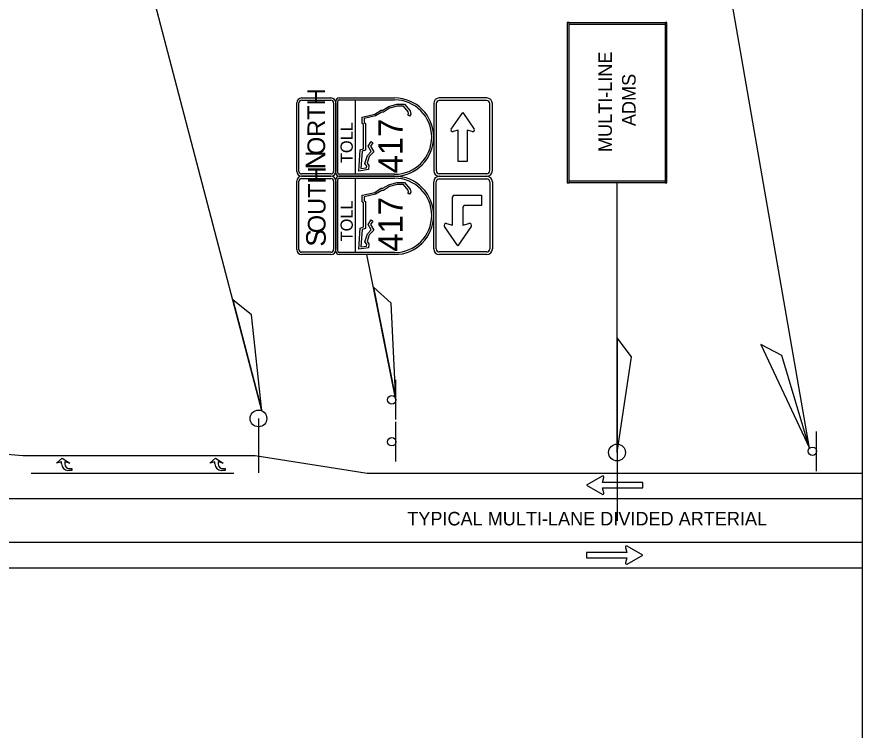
# Model space of a CAD drawing. Extents: x -830008.4 to -829992.7, y 1290284.1 to 1290294.4.
# Drawn here: x -829997.148 to -829992.774, y 1290288.685 to 1290292.375 of the extents above; entities that cross this region are included whole.
import ezdxf

# ---------------------------------------------------------------- set-up
doc = ezdxf.new("R2010")
doc.units = 0
for name, color, linetype in [('DirArrowsPavt', 7, 'Continuous'), ('LaneDirArrow', 7, 'Continuous'), ('LeaderLine_dp', 7, 'Continuous'), ('NonPlottingEle_dp', 7, 'Continuous'), ('SignPanel', 7, 'Continuous'), ('SignSupport', 7, 'Continuous'), ('SignTruss', 7, 'Continuous'), ('TextLabel', 7, 'Continuous')]:
    doc.layers.add(name, color=color, linetype=linetype)

msp = doc.modelspace()

# ---------------------------------------------------------------- linework, layer by layer
at = {"layer": 'DirArrowsPavt'}
for p, q in [((-829996.8778, 1290290.0388), (-829996.8642, 1290290.0388)), ((-829996.0841, 1290290.0388), (-829996.0704, 1290290.0388))]:
    msp.add_line(p, q, dxfattribs=at)
for points in [[(-829996.9175, 1290290.0616), (-829996.9175, 1290290.0721), (-829996.9442, 1290290.0655), (-829996.9142, 1290290.0921), (-829996.8742, 1290290.0655), (-829996.9008, 1290290.0721), (-829996.9008, 1290290.0618)], [(-829996.1237, 1290290.0616), (-829996.1237, 1290290.0721), (-829996.1504, 1290290.0655), (-829996.1204, 1290290.0921), (-829996.0804, 1290290.0655), (-829996.1071, 1290290.0721), (-829996.1071, 1290290.0618)], [(-829996.8642, 1290290.0388), (-829996.8642, 1290290.0288), (-829996.8847, 1290290.0288)], [(-829996.0704, 1290290.0388), (-829996.0704, 1290290.0288), (-829996.0909, 1290290.0288)]]:
    msp.add_lwpolyline(points, dxfattribs=at)
for centre, radius in [((-829996.8847, 1290290.0616), 0.0328), ((-829996.8778, 1290290.0618), 0.023), ((-829996.0909, 1290290.0616), 0.0328), ((-829996.0841, 1290290.0618), 0.023)]:
    msp.add_arc(centre, radius, 180, 270, dxfattribs=at)
at = {"layer": 'LaneDirArrow'}
for p, q in [((-829994.1196, 1290289.9986), (-829994.2004, 1290289.952)), ((-829994.1173, 1290289.9659), (-829994.1105, 1290289.9916)), ((-829993.9087, 1290289.9659), (-829994.1173, 1290289.9659)), ((-829993.9087, 1290289.9381), (-829993.9087, 1290289.9659)), ((-829994.2004, 1290289.952), (-829994.1196, 1290289.9054)), ((-829994.1173, 1290289.9381), (-829993.9087, 1290289.9381)), ((-829994.1105, 1290289.9124), (-829994.1173, 1290289.9381)), ((-829993.9986, 1290289.6301), (-829993.9917, 1290289.6044)), ((-829993.9087, 1290289.5905), (-829993.9895, 1290289.6372)), ((-829993.9917, 1290289.6044), (-829994.2004, 1290289.6044)), ((-829994.2004, 1290289.6044), (-829994.2004, 1290289.5767)), ((-829994.2004, 1290289.5767), (-829993.9917, 1290289.5767)), ((-829993.9917, 1290289.5767), (-829993.9986, 1290289.551)), ((-829993.9895, 1290289.5439), (-829993.9087, 1290289.5905))]:
    msp.add_line(p, q, dxfattribs=at)
for centre, start, end in [((-829994.1165, 1290289.9932), 345, 120), ((-829994.1165, 1290289.9108), 240, 15), ((-829993.9926, 1290289.6318), 60, 195), ((-829993.9926, 1290289.5493), 165, 300)]:
    msp.add_arc(centre, 0.00625, start, end, dxfattribs=at)
at = {"layer": 'LeaderLine_dp'}
for p, q in [((-829995.2111, 1290290.8933), (-829995.3033, 1290290.9757)), ((-829995.3033, 1290290.9757), (-829995.1866, 1290290.3939)), ((-829995.9337, 1290290.8338), (-829996.0305, 1290290.9106)), ((-829996.0305, 1290290.9106), (-829995.8801, 1290290.3367)), ((-829995.1866, 1290290.3939), (-829995.2111, 1290290.8933)), ((-829995.8801, 1290290.3367), (-829995.9337, 1290290.8338)), ((-829993.9683, 1290290.6153), (-829994.0424, 1290290.7142)), ((-829994.0424, 1290290.7142), (-829994.0424, 1290290.1209)), ((-829993.189, 1290290.6224), (-829993.298, 1290290.6806)), ((-829993.298, 1290290.6806), (-829993.0471, 1290290.1429)), ((-829994.0424, 1290290.1209), (-829993.9683, 1290290.6153)), ((-829993.0471, 1290290.1429), (-829993.189, 1290290.6224))]:
    msp.add_line(p, q, dxfattribs=at)
at = {"layer": 'NonPlottingEle_dp'}
msp.add_lwpolyline([(-830007.4742, 1290294.228), (-829992.7742, 1290294.228), (-829992.7742, 1290285.328), (-830007.4742, 1290285.328)], close=True, dxfattribs=at)
at = {"layer": 'SignPanel'}
for p, q in [((-829995.2966, 1290291.8721), (-829995.2632, 1290291.8929)), ((-829995.2602, 1290291.8823), (-829995.2925, 1290291.8622)), ((-829995.2632, 1290291.8929), (-829995.2548, 1290291.8929)), ((-829995.2518, 1290291.8823), (-829995.2602, 1290291.8823)), ((-829995.2548, 1290291.8929), (-829995.2238, 1290291.9117)), ((-829995.2196, 1290291.9019), (-829995.2518, 1290291.8823)), ((-829995.2238, 1290291.9117), (-829995.1814, 1290291.9233)), ((-829995.18, 1290291.9127), (-829995.2196, 1290291.9019)), ((-829995.1814, 1290291.9233), (-829995.1418, 1290291.9233)), ((-829995.1468, 1290291.9127), (-829995.18, 1290291.9127)), ((-829995.1232, 1290291.8839), (-829995.1468, 1290291.9127)), ((-829995.1418, 1290291.9233), (-829995.1135, 1290291.8887)), ((-829995.1209, 1290291.8745), (-829995.1232, 1290291.8839)), ((-829995.1135, 1290291.8887), (-829995.1095, 1290291.8723)), ((-829994.9003, 1290291.7947), (-829994.8411, 1290291.8809)), ((-829994.8411, 1290291.8809), (-829994.7819, 1290291.7947)), ((-829995.3624, 1290291.8568), (-829995.2966, 1290291.8721)), ((-829995.3624, 1290291.823), (-829995.3624, 1290291.8568)), ((-829995.2925, 1290291.8622), (-829995.3518, 1290291.8484)), ((-829995.3518, 1290291.8484), (-829995.3518, 1290291.8286)), ((-829995.1254, 1290291.8679), (-829995.1209, 1290291.8745)), ((-829995.1168, 1290291.8619), (-829995.1254, 1290291.8679)), ((-829995.1095, 1290291.8723), (-829995.1168, 1290291.8619)), ((-829995.3554, 1290291.8183), (-829995.3624, 1290291.823)), ((-829995.3554, 1290291.6929), (-829995.3554, 1290291.8183)), ((-829995.3518, 1290291.8286), (-829995.3448, 1290291.8239)), ((-829995.3448, 1290291.8239), (-829995.3448, 1290291.6857)), ((-829994.8639, 1290291.7895), (-829994.8907, 1290291.7815)), ((-829994.8639, 1290291.6271), (-829994.8639, 1290291.7895)), ((-829994.7915, 1290291.7815), (-829994.8183, 1290291.7895)), ((-829994.8183, 1290291.7895), (-829994.8183, 1290291.6271)), ((-829995.3313, 1290291.7065), (-829995.3158, 1290291.7293)), ((-829995.3148, 1290291.6784), (-829995.3313, 1290291.7065)), ((-829995.3071, 1290291.7234), (-829995.3188, 1290291.7061)), ((-829995.3188, 1290291.7061), (-829995.3017, 1290291.677)), ((-829995.3158, 1290291.7293), (-829995.3071, 1290291.7234)), ((-829995.3795, 1290291.5774), (-829995.3711, 1290291.6868)), ((-829995.3711, 1290291.6868), (-829995.3554, 1290291.6929)), ((-829995.3611, 1290291.6793), (-829995.368, 1290291.5899)), ((-829995.3448, 1290291.6857), (-829995.3611, 1290291.6793)), ((-829995.334, 1290291.6577), (-829995.3148, 1290291.6784)), ((-829995.3017, 1290291.677), (-829995.3247, 1290291.6522)), ((-829995.3477, 1290291.6155), (-829995.334, 1290291.6577)), ((-829995.3247, 1290291.6522), (-829995.3359, 1290291.6176)), ((-829994.8183, 1290291.6271), (-829994.8639, 1290291.6271)), ((-829995.3295, 1290291.5852), (-829995.3795, 1290291.5774)), ((-829995.368, 1290291.5899), (-829995.339, 1290291.5944)), ((-829995.3379, 1290291.6031), (-829995.3477, 1290291.6155)), ((-829995.339, 1290291.5944), (-829995.3379, 1290291.6031)), ((-829995.3359, 1290291.6176), (-829995.3269, 1290291.6061)), ((-829995.3269, 1290291.6061), (-829995.3295, 1290291.5852)), ((-829995.2966, 1290291.4671), (-829995.2632, 1290291.4879)), ((-829995.2632, 1290291.4879), (-829995.2548, 1290291.4879)), ((-829995.2548, 1290291.4879), (-829995.2238, 1290291.5067)), ((-829995.2196, 1290291.4969), (-829995.2518, 1290291.4773)), ((-829995.2238, 1290291.5067), (-829995.1814, 1290291.5183)), ((-829995.18, 1290291.5077), (-829995.2196, 1290291.4969)), ((-829995.1814, 1290291.5183), (-829995.1418, 1290291.5183)), ((-829995.1468, 1290291.5077), (-829995.18, 1290291.5077)), ((-829995.1232, 1290291.4789), (-829995.1468, 1290291.5077)), ((-829995.1418, 1290291.5183), (-829995.1135, 1290291.4837)), ((-829995.3624, 1290291.4518), (-829995.2966, 1290291.4671)), ((-829995.3624, 1290291.418), (-829995.3624, 1290291.4518)), ((-829995.2925, 1290291.4572), (-829995.3518, 1290291.4434)), ((-829995.3518, 1290291.4434), (-829995.3518, 1290291.4236)), ((-829995.2602, 1290291.4773), (-829995.2925, 1290291.4572)), ((-829995.2518, 1290291.4773), (-829995.2602, 1290291.4773)), ((-829995.1254, 1290291.4629), (-829995.1209, 1290291.4695)), ((-829995.1168, 1290291.4569), (-829995.1254, 1290291.4629)), ((-829995.1209, 1290291.4695), (-829995.1232, 1290291.4789)), ((-829995.1095, 1290291.4673), (-829995.1168, 1290291.4569)), ((-829995.1135, 1290291.4837), (-829995.1095, 1290291.4673)), ((-829994.8935, 1290291.2964), (-829994.8935, 1290291.4436)), ((-829994.8854, 1290291.4517), (-829994.7446, 1290291.4517)), ((-829994.7446, 1290291.4517), (-829994.7446, 1290291.3986)), ((-829995.3554, 1290291.4133), (-829995.3624, 1290291.418)), ((-829995.3554, 1290291.2879), (-829995.3554, 1290291.4133)), ((-829995.3518, 1290291.4236), (-829995.3448, 1290291.4189)), ((-829995.3448, 1290291.4189), (-829995.3448, 1290291.2807)), ((-829994.8403, 1290291.3905), (-829994.8403, 1290291.2964)), ((-829994.7446, 1290291.3986), (-829994.8322, 1290291.3986)), ((-829995.3313, 1290291.3015), (-829995.3158, 1290291.3243)), ((-829995.3071, 1290291.3184), (-829995.3188, 1290291.3011)), ((-829995.3158, 1290291.3243), (-829995.3071, 1290291.3184)), ((-829995.3795, 1290291.1724), (-829995.3711, 1290291.2818)), ((-829995.3711, 1290291.2818), (-829995.3554, 1290291.2879)), ((-829995.3611, 1290291.2743), (-829995.368, 1290291.1849)), ((-829995.3448, 1290291.2807), (-829995.3611, 1290291.2743)), ((-829995.334, 1290291.2527), (-829995.3148, 1290291.2734)), ((-829995.3148, 1290291.2734), (-829995.3313, 1290291.3015)), ((-829995.3017, 1290291.272), (-829995.3247, 1290291.2472)), ((-829995.3188, 1290291.3011), (-829995.3017, 1290291.272)), ((-829994.8669, 1290291.1897), (-829994.936, 1290291.2903)), ((-829994.9247, 1290291.3057), (-829994.8935, 1290291.2964)), ((-829994.7978, 1290291.2903), (-829994.8669, 1290291.1897)), ((-829994.8403, 1290291.2964), (-829994.809, 1290291.3057)), ((-829995.3477, 1290291.2105), (-829995.334, 1290291.2527)), ((-829995.3247, 1290291.2472), (-829995.3359, 1290291.2126)), ((-829995.368, 1290291.1849), (-829995.339, 1290291.1894)), ((-829995.3379, 1290291.1981), (-829995.3477, 1290291.2105)), ((-829995.339, 1290291.1894), (-829995.3379, 1290291.1981)), ((-829995.3359, 1290291.2126), (-829995.3269, 1290291.2011)), ((-829995.3269, 1290291.2011), (-829995.3295, 1290291.1802)), ((-829995.3295, 1290291.1802), (-829995.3795, 1290291.1724))]:
    msp.add_line(p, q, dxfattribs=at)
for points in [[(-829994.3009, 1290292.346), (-829994.3009, 1290291.516), (-829994.2909, 1290291.516), (-829994.2909, 1290292.346)], [(-829993.794, 1290292.346), (-829993.794, 1290292.336), (-829994.2909, 1290292.336), (-829994.2909, 1290292.346)], [(-829993.784, 1290291.516), (-829993.784, 1290292.346), (-829993.794, 1290292.346), (-829993.794, 1290291.516)], [(-829994.2909, 1290291.516), (-829994.2909, 1290291.526), (-829993.794, 1290291.526), (-829993.794, 1290291.516)]]:
    msp.add_lwpolyline(points, close=True, dxfattribs=at)
for points in [[(-829995.7002, 1290291.5757), (-829995.7002, 1290291.9301)], [(-829995.6886, 1290291.5757), (-829995.6886, 1290291.9301)], [(-829995.6749, 1290291.9554), (-829995.523, 1290291.9554)], [(-829995.6749, 1290291.9438), (-829995.523, 1290291.9438)], [(-829995.5093, 1290291.9301), (-829995.5093, 1290291.5757)], [(-829995.4977, 1290291.5673), (-829995.4977, 1290291.9385)], [(-829995.4977, 1290291.9301), (-829995.4977, 1290291.5757)], [(-829995.4875, 1290291.5673), (-829995.4875, 1290291.9385)], [(-829995.4808, 1290291.9554), (-829995.1939, 1290291.9554)], [(-829995.4808, 1290291.9453), (-829995.1939, 1290291.9453)], [(-829995.3964, 1290291.5605), (-829995.3964, 1290291.9453)], [(-829994.9914, 1290291.9265), (-829994.9914, 1290291.5793)], [(-829994.9782, 1290291.9265), (-829994.9782, 1290291.5793)], [(-829994.7166, 1290291.9554), (-829994.9625, 1290291.9554)], [(-829994.7166, 1290291.9421), (-829994.9625, 1290291.9421)], [(-829994.7009, 1290291.5793), (-829994.7009, 1290291.9265)], [(-829994.6877, 1290291.5793), (-829994.6877, 1290291.9265)], [(-829995.523, 1290291.562), (-829995.6749, 1290291.562)], [(-829995.6749, 1290291.5504), (-829995.523, 1290291.5504)], [(-829995.523, 1290291.5504), (-829995.6749, 1290291.5504)], [(-829995.6749, 1290291.5388), (-829995.523, 1290291.5388)], [(-829995.4977, 1290291.1623), (-829995.4977, 1290291.5335)], [(-829995.4875, 1290291.1623), (-829995.4875, 1290291.5335)], [(-829995.1939, 1290291.5605), (-829995.4808, 1290291.5605)], [(-829995.1939, 1290291.5504), (-829995.4808, 1290291.5504)], [(-829995.4808, 1290291.5504), (-829995.1939, 1290291.5504)], [(-829995.4808, 1290291.5403), (-829995.1939, 1290291.5403)], [(-829995.3964, 1290291.1555), (-829995.3964, 1290291.5403)], [(-829994.9625, 1290291.5637), (-829994.7166, 1290291.5637)], [(-829994.9625, 1290291.5504), (-829994.7166, 1290291.5504)], [(-829994.9625, 1290291.5504), (-829994.7166, 1290291.5504)], [(-829994.9625, 1290291.5371), (-829994.7166, 1290291.5371)], [(-829995.7002, 1290291.1707), (-829995.7002, 1290291.5251)], [(-829995.6886, 1290291.1707), (-829995.6886, 1290291.5251)], [(-829995.5093, 1290291.5251), (-829995.5093, 1290291.1707)], [(-829995.4977, 1290291.5251), (-829995.4977, 1290291.1707)], [(-829994.9914, 1290291.1743), (-829994.9914, 1290291.5215)], [(-829994.9782, 1290291.1743), (-829994.9782, 1290291.5215)], [(-829994.7009, 1290291.5215), (-829994.7009, 1290291.1743)], [(-829994.6877, 1290291.5215), (-829994.6877, 1290291.1743)], [(-829995.523, 1290291.157), (-829995.6749, 1290291.157)], [(-829995.523, 1290291.1454), (-829995.6749, 1290291.1454)], [(-829995.1939, 1290291.1555), (-829995.4808, 1290291.1555)], [(-829995.1939, 1290291.1454), (-829995.4808, 1290291.1454)], [(-829994.7166, 1290291.1587), (-829994.9625, 1290291.1587)], [(-829994.7166, 1290291.1454), (-829994.9625, 1290291.1454)]]:
    msp.add_lwpolyline(points, dxfattribs=at)
for centre, radius, start, end in [((-829995.6749, 1290291.9301), 0.0253, 90, 180), ((-829995.6749, 1290291.9301), 0.0137, 90, 180), ((-829995.523, 1290291.9301), 0.0253, 0, 90), ((-829995.523, 1290291.9301), 0.0137, 0, 90), ((-829995.4808, 1290291.9385), 0.0169, 90, 180), ((-829995.4808, 1290291.9385), 0.00675, 90, 180), ((-829995.1939, 1290291.7529), 0.2025, 270, 90), ((-829995.1939, 1290291.7529), 0.1924, 270, 90), ((-829994.9625, 1290291.9265), 0.0289, 90, 180), ((-829994.9625, 1290291.9265), 0.0157, 90.0544, 180), ((-829994.7166, 1290291.9265), 0.0289, 0, 90), ((-829994.7166, 1290291.9265), 0.0157, 0, 90), ((-829994.8932, 1290291.7898), 0.00868, 145.5119, 286.6443), ((-829994.789, 1290291.7898), 0.00868, 253.3557, 34.4881), ((-829995.6749, 1290291.5757), 0.0253, 180, 270), ((-829995.6749, 1290291.5757), 0.0137, 180, 270), ((-829995.523, 1290291.5757), 0.0253, 270, 0), ((-829995.523, 1290291.5757), 0.0137, 270, 0), ((-829994.9625, 1290291.5793), 0.0289, 180, 270), ((-829994.9625, 1290291.5793), 0.0157, 180, 269.9456), ((-829994.7166, 1290291.5793), 0.0157, 270, 360), ((-829994.7166, 1290291.5793), 0.0289, 270, 360), ((-829995.6749, 1290291.5251), 0.0253, 90, 180), ((-829995.6749, 1290291.5251), 0.0137, 90, 180), ((-829995.523, 1290291.5251), 0.0253, 0, 90), ((-829995.523, 1290291.5251), 0.0137, 0, 90), ((-829995.4808, 1290291.5673), 0.0169, 180, 270), ((-829995.4808, 1290291.5335), 0.0169, 90, 180), ((-829995.4808, 1290291.5673), 0.00675, 180, 270), ((-829995.4808, 1290291.5335), 0.00675, 90, 180), ((-829995.1939, 1290291.3479), 0.2025, 270, 90), ((-829995.1939, 1290291.3479), 0.1924, 270, 90), ((-829994.9625, 1290291.5215), 0.0289, 90, 180), ((-829994.9625, 1290291.5215), 0.0157, 90.0544, 180), ((-829994.7166, 1290291.5215), 0.0289, 0, 90), ((-829994.7166, 1290291.5215), 0.0157, 0, 90), ((-829994.8854, 1290291.4436), 0.0081, 90, 180), ((-829994.8322, 1290291.3905), 0.0081, 90, 180), ((-829994.9276, 1290291.296), 0.0101, 73.3557, 214.4881), ((-829994.8061, 1290291.296), 0.0101, 325.5119, 106.6443), ((-829995.6749, 1290291.1707), 0.0253, 180, 270), ((-829995.6749, 1290291.1707), 0.0137, 180, 270), ((-829995.523, 1290291.1707), 0.0253, 270, 360), ((-829995.523, 1290291.1707), 0.0137, 270, 360), ((-829995.4808, 1290291.1623), 0.0169, 180, 270), ((-829995.4808, 1290291.1623), 0.00675, 180, 270), ((-829994.9625, 1290291.1743), 0.0289, 180, 270), ((-829994.9625, 1290291.1743), 0.0157, 180, 269.9456), ((-829994.7166, 1290291.1743), 0.0289, 270, 360), ((-829994.7166, 1290291.1743), 0.0157, 270, 360)]:
    msp.add_arc(centre, radius, start, end, dxfattribs=at)
at = {"layer": 'SignSupport'}
for p, q in [((-829995.1866, 1290290.291), (-829995.1866, 1290290.4968)), ((-829995.1866, 1290290.074), (-829995.1866, 1290290.2798)), ((-829993.0094, 1290290.0244), (-829993.0094, 1290290.2302))]:
    msp.add_line(p, q, dxfattribs=at)
for centre in [(-829995.2087, 1290290.3939), (-829995.2087, 1290290.1769), (-829993.0315, 1290290.1273)]:
    msp.add_circle(centre, 0.0221, dxfattribs=at)
at = {"layer": 'SignTruss'}
for p, q in [((-829995.8985, 1290290.2973), (-829995.8985, 1290290.0166)), ((-829994.0424, 1290290.1209), (-829994.0424, 1290289.7674))]:
    msp.add_line(p, q, dxfattribs=at)
for centre in [(-829995.8985, 1290290.2973), (-829995.8985, 1290290.2973), (-829994.0424, 1290290.1209)]:
    msp.add_circle(centre, 0.0434, dxfattribs=at)
at = {"layer": 'TextLabel'}
for p, q in [((-829993.0471, 1290290.1429), (-829993.4953, 1290292.7228)), ((-829995.8801, 1290290.3367), (-829996.4857, 1290292.6472)), ((-829994.0424, 1290290.1209), (-829994.0424, 1290291.516)), ((-829995.1866, 1290290.3939), (-829995.3374, 1290291.1454)), ((-829997.0749, 1290290.1056), (-829995.9149, 1290290.1056)), ((-829995.9149, 1290290.1056), (-829995.3349, 1290290.0133)), ((-829997.0749, 1290290.0133), (-829996.0258, 1290290.0133)), ((-829995.3349, 1290290.0133), (-829992.7742, 1290290.0133)), ((-829998.578, 1290289.8838), (-829993.659, 1290289.8838)), ((-829993.659, 1290289.8838), (-829992.7742, 1290289.8838)), ((-829998.4483, 1290289.6579), (-829992.7742, 1290289.6579)), ((-829997.6499, 1290289.5251), (-829992.7742, 1290289.5251))]:
    msp.add_line(p, q, dxfattribs=at)
msp.add_arc((-829997.0749, 1290291.317), 1.2114, 238.3217, 270, dxfattribs=at)

# ---------------------------------------------------------------- texts
at = {"layer": 'SignPanel'}
for s, height, p in [('ORTH', 0.09113, (-829995.5535, 1290291.6598)), ('417', 0.12656, (-829995.1517, 1290291.5655)), ('TOLL', 0.06328, (-829995.4103, 1290291.6185)), ('N', 0.1013, (-829995.5523, 1290291.5859)), ('OUTH', 0.09113, (-829995.5511, 1290291.2555)), ('TOLL', 0.06328, (-829995.4103, 1290291.2135)), ('417', 0.12656, (-829995.1517, 1290291.1605)), ('S', 0.1013, (-829995.55, 1290291.1862))]:
    msp.add_text(s, height=height, rotation=90, dxfattribs=at).set_placement(p)
at = {"layer": 'TextLabel'}
for s, rotation, p in [('MULTI-LINE', 90.0044, (-829994.0687, 1290291.6755)), ('ADMS', 90.0044, (-829993.9462, 1290291.8097)), ('TYPICAL MULTI-LANE DIVIDED ARTERIAL', 0.0044, (-829995.128, 1290289.7439))]:
    msp.add_text(s, height=0.07, rotation=rotation, dxfattribs=at).set_placement(p)

doc.saveas('drawing.dxf')
